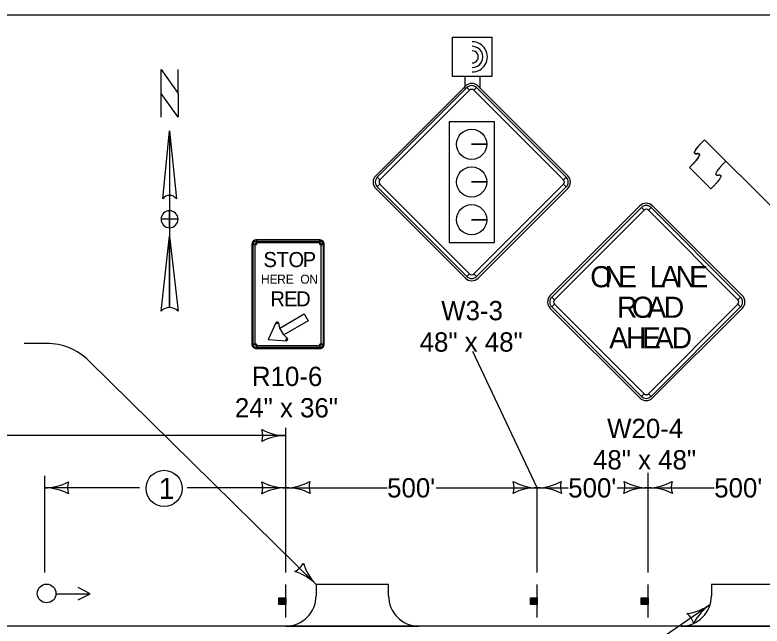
# Model space of a CAD drawing. Extents: x -2134934 to -2122394, y -2140205 to -2137036.
# Drawn here: x -2128036 to -2127418, y -2137542 to -2137036 of the extents above; entities that cross this region are included whole.
import ezdxf

# ---------------------------------------------------------------- set-up
doc = ezdxf.new("R2010")
doc.units = 0
for name, color, linetype in [('Barrier', 7, 'Continuous'), ('BridgeSuperStructureExisting', 7, 'Continuous'), ('Default', 7, 'Continuous'), ('dsnCellsScaleBlock', 7, 'Continuous'), ('DsnShtPlotIdentification', 7, 'Continuous'), ('DsnShtPlotShape', 7, 'Continuous'), ('TC_Barrier', 7, 'Continuous')]:
    doc.layers.add(name, color=color, linetype=linetype)

msp = doc.modelspace()

# ---------------------------------------------------------------- linework, layer by layer
at = {"layer": 'Barrier'}
for p, q in [((-2127663.33, -2137094.84), (-2127737.58, -2137169.09)), ((-2127662.01, -2137096.17), (-2127659.8, -2137098.38)), ((-2127656.26, -2137098.38), (-2127654.05, -2137096.17)), ((-2127578.48, -2137169.09), (-2127652.73, -2137094.84)), ((-2127645.62, -2137143.06), (-2127658.12, -2137143.06)), ((-2127658.12, -2137143.06), (-2127645.62, -2137143.06)), ((-2127407.97, -2137196.68), (-2127465.31, -2137139.38)), ((-2127465.31, -2137139.38), (-2127447.62, -2137157.06)), ((-2127460, -2137180.05), (-2127477.68, -2137162.37)), ((-2127734.04, -2137172.63), (-2127736.25, -2137170.42)), ((-2127579.81, -2137170.42), (-2127582.02, -2137172.63)), ((-2127737.58, -2137179.7), (-2127663.33, -2137253.94)), ((-2127736.25, -2137178.37), (-2127734.04, -2137176.16)), ((-2127645.62, -2137174.31), (-2127658.12, -2137174.31)), ((-2127658.12, -2137174.31), (-2127645.62, -2137174.31)), ((-2127652.73, -2137253.94), (-2127578.48, -2137179.7)), ((-2127582.02, -2137176.16), (-2127579.81, -2137178.37)), ((-2127518.85, -2137194.14), (-2127593.09, -2137268.39)), ((-2127517.52, -2137195.47), (-2127515.31, -2137197.68)), ((-2127511.78, -2137197.68), (-2127509.57, -2137195.47)), ((-2127433.99, -2137268.39), (-2127508.24, -2137194.14)), ((-2127645.62, -2137205.56), (-2127658.12, -2137205.56)), ((-2127658.12, -2137205.56), (-2127645.62, -2137205.56)), ((-2127836.37, -2137226.09), (-2127836.37, -2137222.34)), ((-2127836.37, -2137224.84), (-2127836.37, -2137223.27)), ((-2127783.87, -2137222.34), (-2127783.87, -2137226.09)), ((-2127783.87, -2137223.27), (-2127783.87, -2137224.84)), ((-2127840.12, -2137226.09), (-2127836.37, -2137226.09)), ((-2127839.18, -2137226.09), (-2127837.62, -2137226.09)), ((-2127783.87, -2137226.09), (-2127780.12, -2137226.09)), ((-2127782.62, -2137226.09), (-2127781.06, -2137226.09)), ((-2127659.8, -2137250.41), (-2127662.01, -2137252.62)), ((-2127654.05, -2137252.62), (-2127656.26, -2137250.41)), ((-2127589.56, -2137271.93), (-2127591.77, -2137269.72)), ((-2127435.32, -2137269.72), (-2127437.53, -2137271.93)), ((-2127593.09, -2137279), (-2127518.85, -2137353.24)), ((-2127591.77, -2137277.67), (-2127589.56, -2137275.46)), ((-2127508.24, -2137353.24), (-2127433.99, -2137279)), ((-2127437.53, -2137275.46), (-2127435.32, -2137277.67)), ((-2127820.26, -2137291.07), (-2127819.15, -2137291.65)), ((-2127819.15, -2137291.65), (-2127817.93, -2137291.38)), ((-2127810.81, -2137303.72), (-2127811.65, -2137304.64)), ((-2127836.37, -2137308.59), (-2127840.12, -2137308.59)), ((-2127837.62, -2137308.59), (-2127839.18, -2137308.59)), ((-2127836.37, -2137312.34), (-2127836.37, -2137308.59)), ((-2127836.37, -2137311.4), (-2127836.37, -2137309.84)), ((-2127811.65, -2137304.64), (-2127811.7, -2137305.89)), ((-2127780.12, -2137308.59), (-2127783.87, -2137308.59)), ((-2127783.87, -2137308.59), (-2127783.87, -2137312.34)), ((-2127783.87, -2137309.84), (-2127783.87, -2137311.4)), ((-2127781.06, -2137308.59), (-2127782.62, -2137308.59)), ((-2127515.31, -2137349.71), (-2127517.52, -2137351.92)), ((-2127509.57, -2137351.92), (-2127511.78, -2137349.71))]:
    msp.add_line(p, q, dxfattribs=at)
for points in [[(-2127662.01, -2137096.17), (-2127736.25, -2137170.42), (-2127734.04, -2137172.63), (-2127659.8, -2137098.38), (-2127662.01, -2137096.17)], [(-2127579.81, -2137170.42), (-2127654.05, -2137096.17), (-2127656.26, -2137098.38), (-2127582.02, -2137172.63), (-2127579.81, -2137170.42)], [(-2127639.3, -2137124.45), (-2127676.76, -2137124.45), (-2127676.76, -2137224.34), (-2127639.3, -2137224.34), (-2127639.3, -2137124.45)], [(-2127736.25, -2137178.37), (-2127662.01, -2137252.62), (-2127659.8, -2137250.41), (-2127734.04, -2137176.16), (-2127736.25, -2137178.37)], [(-2127654.05, -2137252.62), (-2127579.81, -2137178.37), (-2127582.02, -2137176.16), (-2127656.26, -2137250.41), (-2127654.05, -2137252.62)], [(-2127517.52, -2137195.47), (-2127591.77, -2137269.72), (-2127589.56, -2137271.93), (-2127515.31, -2137197.68), (-2127517.52, -2137195.47)], [(-2127435.32, -2137269.72), (-2127509.57, -2137195.47), (-2127511.78, -2137197.68), (-2127437.53, -2137271.93), (-2127435.32, -2137269.72)], [(-2127836.37, -2137312.34), (-2127783.87, -2137312.34), (-2127783.87, -2137308.59), (-2127780.12, -2137308.59), (-2127780.12, -2137226.09), (-2127783.87, -2137226.09), (-2127783.87, -2137222.34), (-2127836.37, -2137222.34), (-2127836.37, -2137226.09), (-2127840.12, -2137226.09), (-2127840.12, -2137308.59), (-2127836.37, -2137308.59), (-2127836.37, -2137312.34)], [(-2127783.87, -2137224.84), (-2127836.37, -2137224.84), (-2127836.37, -2137223.27), (-2127783.87, -2137223.27), (-2127783.87, -2137224.84)], [(-2127837.62, -2137226.09), (-2127837.62, -2137308.59), (-2127839.18, -2137308.59), (-2127839.18, -2137226.09), (-2127837.62, -2137226.09)], [(-2127782.62, -2137308.59), (-2127782.62, -2137226.09), (-2127781.06, -2137226.09), (-2127781.06, -2137308.59), (-2127782.62, -2137308.59)], [(-2127591.77, -2137277.67), (-2127517.52, -2137351.92), (-2127515.31, -2137349.71), (-2127589.56, -2137275.46), (-2127591.77, -2137277.67)], [(-2127509.57, -2137351.92), (-2127435.32, -2137277.67), (-2127437.53, -2137275.46), (-2127511.78, -2137349.71), (-2127509.57, -2137351.92)], [(-2127796.75, -2137283.59), (-2127793.47, -2137289.27), (-2127813.77, -2137300.99), (-2127817.05, -2137295.31), (-2127796.75, -2137283.59)], [(-2127826.77, -2137304.71), (-2127811.7, -2137305.89), (-2127811.65, -2137304.64), (-2127810.81, -2137303.72), (-2127813.77, -2137300.99), (-2127817.05, -2137295.31), (-2127817.93, -2137291.38), (-2127819.15, -2137291.65), (-2127820.26, -2137291.07), (-2127826.77, -2137304.71)], [(-2127836.37, -2137309.84), (-2127783.87, -2137309.84), (-2127783.87, -2137311.4), (-2127836.37, -2137311.4), (-2127836.37, -2137309.84)]]:
    msp.add_lwpolyline(points, close=True, dxfattribs=at)
for centre in [(-2127658.12, -2137143.06), (-2127658.12, -2137174.31), (-2127658.12, -2137205.56)]:
    msp.add_circle(centre, 12.5, dxfattribs=at)
for centre, radius, start, end in [((-2127658.03, -2137100.15), 7.5, 44.99999, 134.99974), ((-2127658.03, -2137100.15), 5.62, 44.99999, 134.99974), ((-2127658.03, -2137100.15), 2.5, 44.99999, 134.99974), ((-2127732.28, -2137174.39), 7.5, 134.99974, 224.99995), ((-2127732.28, -2137174.39), 5.62, 134.99974, 224.99995), ((-2127732.28, -2137174.39), 2.5, 134.99974, 224.99995), ((-2127583.79, -2137174.39), 2.5, 315.00016, 44.9998), ((-2127583.79, -2137174.39), 5.62, 315.00016, 44.9998), ((-2127583.79, -2137174.39), 7.5, 315.00016, 44.9998), ((-2127513.54, -2137199.45), 7.5, 44.99999, 134.99974), ((-2127513.54, -2137199.45), 5.62, 44.99999, 134.99974), ((-2127513.54, -2137199.45), 2.5, 44.99999, 134.99974), ((-2127836.37, -2137226.09), 3.75, 90.00021, 179.99985), ((-2127836.37, -2137226.09), 2.81, 90.00021, 179.99985), ((-2127783.87, -2137226.09), 3.75, 0, 90.00021), ((-2127783.87, -2137226.09), 2.81, 0, 90.00021), ((-2127836.37, -2137226.09), 1.25, 90.00021, 179.99985), ((-2127783.87, -2137226.09), 1.25, 0, 90.00021), ((-2127658.03, -2137248.64), 7.5, 224.99995, 315.00016), ((-2127658.03, -2137248.64), 5.62, 224.99995, 315.00016), ((-2127658.03, -2137248.64), 2.5, 224.99995, 315.00016), ((-2127587.79, -2137273.69), 7.5, 134.99974, 224.99995), ((-2127587.79, -2137273.69), 5.62, 134.99974, 224.99995), ((-2127587.79, -2137273.69), 2.5, 134.99974, 224.99995), ((-2127439.3, -2137273.69), 2.5, 315.00016, 44.9998), ((-2127439.3, -2137273.69), 5.62, 315.00016, 44.9998), ((-2127439.3, -2137273.69), 7.5, 315.00016, 44.9998), ((-2127819.15, -2137291.65), 1.25, 12.62232, 152.27557), ((-2127811.65, -2137304.64), 1.25, 267.72427, 47.37758), ((-2127836.37, -2137308.59), 3.75, 179.99985, 270.00006), ((-2127836.37, -2137308.59), 2.81, 179.99985, 270.00006), ((-2127836.37, -2137308.59), 1.25, 179.99985, 270.00006), ((-2127783.87, -2137308.59), 3.75, 270.00006, 0.00027), ((-2127783.87, -2137308.59), 2.81, 270.00006, 0.00027), ((-2127783.87, -2137308.59), 1.25, 270.00006, 0.00027), ((-2127513.54, -2137347.94), 7.5, 224.99995, 315.00016), ((-2127513.54, -2137347.94), 5.62, 224.99995, 315.00016), ((-2127513.54, -2137347.94), 2.5, 224.99995, 315.00016)]:
    msp.add_arc(centre, radius, start, end, dxfattribs=at)
for points in [[(-2127477.68, -2137162.37), (-2127465.31, -2137149.99), (-2127477.68, -2137151.77), (-2127465.31, -2137139.38)], [(-2127447.62, -2137157.06), (-2127460, -2137169.44), (-2127447.63, -2137167.67), (-2127460, -2137180.05)]]:
    msp.add_open_spline(points, degree=2, dxfattribs=at)
at = {"layer": 'BridgeSuperStructureExisting'}
for p, q in [((-2127663.87, -2137086.93), (-2127663.87, -2137096.93)), ((-2127651.37, -2137086.93), (-2127651.37, -2137096.93)), ((-2128010.17, -2137308.01), (-2128028.63, -2137308.01)), ((-2127603.79, -2137427.66), (-2127657.13, -2137314.86)), ((-2127975.09, -2137322.38), (-2127786.96, -2137507.67)), ((-2127811.95, -2137497.66), (-2127811.95, -2137377.91)), ((-2127811.95, -2137384.33), (-2128113.68, -2137384.33)), ((-2127511.96, -2137497.66), (-2127511.96, -2137415.16)), ((-2128011.93, -2137417.66), (-2128011.93, -2137497.66)), ((-2127933.15, -2137427.66), (-2128011.93, -2137427.66)), ((-2127811.93, -2137427.66), (-2127893.7, -2137427.66)), ((-2127811.95, -2137427.66), (-2127728.12, -2137427.66)), ((-2127687.62, -2137427.66), (-2127603.79, -2137427.66)), ((-2127603.79, -2137497.66), (-2127603.79, -2137427.66)), ((-2127603.79, -2137427.66), (-2127578.12, -2137427.66)), ((-2127537.62, -2137427.66), (-2127511.96, -2137427.66)), ((-2127511.96, -2137427.66), (-2127457.21, -2137427.66)), ((-2127811.95, -2137535.16), (-2127811.95, -2137507.66)), ((-2127603.79, -2137535.16), (-2127603.79, -2137507.66)), ((-2127511.96, -2137535.16), (-2127511.96, -2137507.66)), ((-2128002.38, -2137515.52), (-2127974.44, -2137515.52)), ((-2127817.28, -2137524.3), (-2127817.28, -2137518.71)), ((-2127816.96, -2137518.71), (-2127816.96, -2137524.3)), ((-2127816.74, -2137524.3), (-2127816.74, -2137518.71)), ((-2127816.42, -2137518.71), (-2127816.42, -2137524.3)), ((-2127816.19, -2137524.3), (-2127816.21, -2137518.71)), ((-2127815.78, -2137518.71), (-2127815.76, -2137524.3)), ((-2127815.56, -2137524.3), (-2127815.56, -2137518.71)), ((-2127815.12, -2137518.71), (-2127815.12, -2137524.3)), ((-2127814.75, -2137524.3), (-2127814.75, -2137518.71)), ((-2127814.43, -2137518.71), (-2127814.41, -2137524.3)), ((-2127814.21, -2137524.3), (-2127814.21, -2137518.71)), ((-2127813.94, -2137518.71), (-2127813.94, -2137524.3)), ((-2127813.61, -2137524.3), (-2127813.61, -2137518.71)), ((-2127813.4, -2137518.71), (-2127813.4, -2137524.3)), ((-2127813.17, -2137524.3), (-2127813.17, -2137518.71)), ((-2127812.91, -2137518.71), (-2127812.91, -2137524.3)), ((-2127812.65, -2137524.3), (-2127812.65, -2137518.71)), ((-2127812.37, -2137518.71), (-2127812.37, -2137524.3)), ((-2127609.12, -2137524.3), (-2127609.12, -2137518.71)), ((-2127608.8, -2137518.71), (-2127608.8, -2137524.3)), ((-2127608.58, -2137524.3), (-2127608.58, -2137518.71)), ((-2127608.26, -2137518.71), (-2127608.26, -2137524.3)), ((-2127608.03, -2137524.3), (-2127608.05, -2137518.71)), ((-2127607.62, -2137518.71), (-2127607.6, -2137524.3)), ((-2127607.4, -2137524.3), (-2127607.4, -2137518.71)), ((-2127606.96, -2137518.71), (-2127606.96, -2137524.3)), ((-2127606.59, -2137524.3), (-2127606.59, -2137518.71)), ((-2127606.27, -2137518.71), (-2127606.25, -2137524.3)), ((-2127606.05, -2137524.3), (-2127606.05, -2137518.71)), ((-2127605.78, -2137518.71), (-2127605.78, -2137524.3)), ((-2127605.45, -2137524.3), (-2127605.45, -2137518.71)), ((-2127605.24, -2137518.71), (-2127605.24, -2137524.3)), ((-2127605.01, -2137524.3), (-2127605.01, -2137518.71)), ((-2127604.75, -2137518.71), (-2127604.75, -2137524.3)), ((-2127604.49, -2137524.3), (-2127604.49, -2137518.71)), ((-2127604.21, -2137518.71), (-2127604.21, -2137524.3)), ((-2127517.28, -2137524.3), (-2127517.28, -2137518.71)), ((-2127516.96, -2137518.71), (-2127516.96, -2137524.3)), ((-2127516.74, -2137524.3), (-2127516.74, -2137518.71)), ((-2127516.42, -2137518.71), (-2127516.42, -2137524.3)), ((-2127516.19, -2137524.3), (-2127516.21, -2137518.71)), ((-2127515.78, -2137518.71), (-2127515.76, -2137524.3)), ((-2127515.56, -2137524.3), (-2127515.56, -2137518.71)), ((-2127515.13, -2137518.71), (-2127515.13, -2137524.3)), ((-2127514.75, -2137524.3), (-2127514.75, -2137518.71)), ((-2127514.43, -2137518.71), (-2127514.41, -2137524.3)), ((-2127514.21, -2137524.3), (-2127514.21, -2137518.71)), ((-2127513.94, -2137518.71), (-2127513.94, -2137524.3)), ((-2127513.61, -2137524.3), (-2127513.61, -2137518.71)), ((-2127513.4, -2137518.71), (-2127513.4, -2137524.3)), ((-2127513.18, -2137524.3), (-2127513.18, -2137518.71)), ((-2127512.91, -2137518.71), (-2127512.91, -2137524.3)), ((-2127512.65, -2137524.3), (-2127512.65, -2137518.71)), ((-2127512.37, -2137518.71), (-2127512.37, -2137524.3)), ((-2127823.33, -2137771.69), (-2127460.63, -2137524.39)), ((-2127811.96, -2137542.16), (-2127701.96, -2137542.16)), ((-2127484.56, -2137542.16), (-2127374.56, -2137542.16))]:
    msp.add_line(p, q, dxfattribs=at)
for points in [[(-2127673.87, -2137086.93), (-2127673.87, -2137054.43), (-2127641.37, -2137054.43), (-2127641.37, -2137086.93)], [(-2127812.05, -2137518.71), (-2127812.05, -2137524.34), (-2127817.67, -2137524.34), (-2127817.67, -2137518.71)], [(-2127603.89, -2137518.71), (-2127603.89, -2137524.34), (-2127609.51, -2137524.34), (-2127609.51, -2137518.71)], [(-2127512.05, -2137518.71), (-2127512.05, -2137524.34), (-2127517.68, -2137524.34), (-2127517.68, -2137518.71)]]:
    msp.add_lwpolyline(points, close=True, dxfattribs=at)
for points in [[(-2127726.96, -2137517.16), (-2127726.96, -2137507.67), (-2127786.96, -2137507.67), (-2127786.96, -2137517.16)], [(-2127399.56, -2137517.16), (-2127399.56, -2137507.67), (-2127459.56, -2137507.67), (-2127459.56, -2137517.16)], [(-2127984.07, -2137520.34), (-2127974.07, -2137515.34), (-2127984.07, -2137510.34)]]:
    msp.add_lwpolyline(points, dxfattribs=at)
for centre, radius in [((-2127912.79, -2137428.16), 15), ((-2128010.12, -2137515.16), 7.74)]:
    msp.add_circle(centre, radius, dxfattribs=at)
for centre, radius, start, end in [((-2127657.61, -2137070.7), 12.5, 269.40414, 90.54446), ((-2127657.61, -2137070.7), 12.5, 269.40414, 90.54446), ((-2127657.61, -2137070.7), 8.75, 269.40414, 90.54446), ((-2127657.61, -2137070.7), 5, 269.40414, 90.54446), ((-2128010.17, -2137358.01), 50, 45.43651, 90), ((-2128011.93, -2137385.16), 42.5, 270, 298.07249), ((-2128011.93, -2137470.16), 42.5, 61.92751, 90), ((-2127976.3, -2137427.66), 16.42, 162.26665, 197.73335), ((-2127847.57, -2137427.66), 16.42, 342.26665, 17.73335), ((-2127811.93, -2137385.16), 42.5, 241.92751, 270), ((-2127811.93, -2137470.16), 42.5, 90, 118.07249), ((-2127812.71, -2137385.17), 42.5, 271.0176, 299.07249), ((-2127811.23, -2137470.15), 42.5, 62.92751, 90.9824), ((-2127776.34, -2137427.04), 16.42, 163.26665, 198.73335), ((-2127639.41, -2137427.04), 16.42, 341.26665, 16.73335), ((-2127604.52, -2137470.15), 42.5, 89.0176, 117.07249), ((-2127603.04, -2137385.17), 42.5, 240.92751, 268.9824), ((-2127604.55, -2137385.17), 42.5, 271.0176, 299.07249), ((-2127603.07, -2137470.15), 42.5, 62.92751, 90.9824), ((-2127568.18, -2137427.04), 16.42, 163.26665, 198.73335), ((-2127547.57, -2137427.04), 16.42, 341.26665, 16.73335), ((-2127512.68, -2137470.15), 42.5, 89.0176, 117.07249), ((-2127511.2, -2137385.17), 42.5, 240.92751, 268.9824), ((-2127512.71, -2137385.17), 42.5, 271.0176, 299.07249), ((-2127511.23, -2137470.15), 42.5, 62.92751, 90.9824), ((-2127476.34, -2137427.04), 16.42, 163.26665, 198.73335), ((-2127811.96, -2137517.16), 25, 270, 0), ((-2127701.96, -2137517.16), 25, 180, 270), ((-2127484.56, -2137517.16), 25, 270, 0)]:
    msp.add_arc(centre, radius, start, end, dxfattribs=at)
at = {"layer": 'Default'}
msp.add_lwpolyline([(-2130231.95, -2137035.95), (-2127096.96, -2137035.95), (-2127096.96, -2139045.94), (-2130231.95, -2139045.94)], close=True, dxfattribs=at)
at = {"layer": 'dsnCellsScaleBlock'}
for p, q in [((-2127908.3, -2137131.92), (-2127902.67, -2137188.26)), ((-2127908.3, -2137131.92), (-2127908.3, -2137278.41)), ((-2127913.93, -2137188.26), (-2127913.93, -2137188.26)), ((-2127913.72, -2137187.74), (-2127912.67, -2137186.56)), ((-2127908.3, -2137212.2), (-2127908.3, -2137212.21)), ((-2127915.34, -2137281.23), (-2127908.3, -2137219.25))]:
    msp.add_line(p, q, dxfattribs=at)
msp.add_lwpolyline([(-2127901.26, -2137120.65), (-2127915.34, -2137100.93), (-2127915.34, -2137081.21), (-2127901.26, -2137100.93)], close=True, dxfattribs=at)
for points in [[(-2127915.34, -2137120.65), (-2127915.34, -2137081.21), (-2127901.26, -2137100.93), (-2127901.26, -2137081.21)], [(-2127913.93, -2137188.26), (-2127908.3, -2137131.92), (-2127908.3, -2137185.44)], [(-2127901.26, -2137205.16), (-2127908.3, -2137205.16), (-2127908.3, -2137198.12)], [(-2127908.3, -2137212.21), (-2127908.3, -2137205.16), (-2127915.34, -2137205.16)], [(-2127908.3, -2137278.41), (-2127908.3, -2137219.25), (-2127901.26, -2137281.22)]]:
    msp.add_lwpolyline(points, dxfattribs=at)
for centre, radius, start, end in [((-2127908.3, -2137192.49), 7.04, 90.02039, 143.12574), ((-2127908.3, -2137192.48), 7.04, 36.84806, 90.02184), ((-2127908.3, -2137205.16), 7.04, 90, 180), ((-2127908.3, -2137205.16), 7.04, 360, 90), ((-2127908.3, -2137205.16), 7.04, 180, 270), ((-2127908.3, -2137205.16), 7.04, 270, 360), ((-2127908.3, -2137288.61), 10.2, 89.98939, 133.61895), ((-2127908.3, -2137288.62), 10.21, 46.40206, 90.00064)]:
    msp.add_arc(centre, radius, start, end, dxfattribs=at)
at = {"layer": 'DsnShtPlotIdentification'}
msp.add_line((-2127160.12, -2137542.16), (-2128660.12, -2137542.16), dxfattribs=at)
msp.add_line((-2127160.12, -2137542.16), (-2128660.12, -2137542.16), dxfattribs=at)
at = {"layer": 'DsnShtPlotShape'}
for centre, radius, start, end in [((-2127847.59, -2137384.37), 16.42, 342.26665, 17.73335), ((-2127811.95, -2137341.87), 42.5, 241.92751, 270), ((-2127811.95, -2137426.87), 42.5, 90, 118.07249), ((-2127812.04, -2137482.35), 16.42, 296.997, 332.46371), ((-2127756.76, -2137477.76), 42.5, 196.65786, 224.73035), ((-2127817.15, -2137537.58), 42.5, 44.73035, 72.80284), ((-2127485, -2137489.57), 42.5, 276.9218, 304.99429), ((-2127436.25, -2137559.2), 42.5, 124.99429, 153.06678), ((-2127489.82, -2137544.82), 16.42, 17.26094, 52.72764)]:
    msp.add_arc(centre, radius, start, end, dxfattribs=at)
at = {"layer": 'TC_Barrier'}
msp.add_line((-2127477.68, -2137162.37), (-2127460, -2137180.05), dxfattribs=at)
for points in [[(-2127465.31, -2137139.38), (-2127477.68, -2137151.77), (-2127465.31, -2137149.99), (-2127477.68, -2137162.37)], [(-2127447.62, -2137157.06), (-2127460, -2137169.44), (-2127447.63, -2137167.67), (-2127460, -2137180.05)]]:
    msp.add_open_spline(points, degree=2, dxfattribs=at)

# ---------------------------------------------------------------- texts
at = {"layer": 'Barrier'}
for s, height, p in [('S', 12.5, (-2127830.57, -2137244.84)), ('T', 12.5, (-2127819.8, -2137244.84)), ('O', 12.5, (-2127809.82, -2137244.84)), ('P', 12.5, (-2127798.07, -2137244.84)), ('O', 17.5, (-2127559.83, -2137261.51)), ('N', 17.5, (-2127548.05, -2137261.51)), ('E', 17.5, (-2127536.83, -2137261.51)), ('L', 17.5, (-2127510.58, -2137261.51)), ('A', 17.5, (-2127501.38, -2137261.51)), ('N', 17.5, (-2127489.11, -2137261.51)), ('E', 17.5, (-2127477.88, -2137261.51)), ('H', 7.5, (-2127832.64, -2137258.59)), ('E', 7.5, (-2127825.49, -2137258.59)), ('R', 7.5, (-2127819.24, -2137258.59)), ('E', 7.5, (-2127812.09, -2137258.59)), ('O', 7.5, (-2127800.02, -2137258.59)), ('N', 7.5, (-2127792.63, -2137258.59)), ('R', 12.5, (-2127824.81, -2137277.34)), ('E', 12.5, (-2127813.48, -2137277.34)), ('D', 12.5, (-2127803.52, -2137277.34)), ('W3-3', 16, (-2127683.32, -2137288.86)), ('R', 17.5, (-2127537.72, -2137286.82)), ('O', 17.5, (-2127525.43, -2137286.82)), ('A', 17.5, (-2127512.59, -2137286.82)), ('D', 17.5, (-2127498.94, -2137286.82)), ('A', 17.5, (-2127544.16, -2137312.13)), ('H', 17.5, (-2127530.29, -2137312.13)), ('E', 17.5, (-2127517.08, -2137312.13)), ('A', 17.5, (-2127506.36, -2137312.13)), ('D', 17.5, (-2127492.5, -2137312.13)), ('48" x 48"', 16, (-2127701.2, -2137314.86)), ('R10-6', 16, (-2127840.05, -2137343.34)), ('24" x 36"', 16, (-2127854.19, -2137369.34)), ('W20-4', 16, (-2127545.91, -2137386.44)), ('48" x 48"', 16, (-2127557.61, -2137412.44))]:
    msp.add_text(s, height=height, dxfattribs=at).set_placement(p)
at = {"layer": 'BridgeSuperStructureExisting'}
for s, height, p in [('1', 17.5, (-2127917.25, -2137436.91)), ("500'", 16, (-2127728.12, -2137435.66)), ("500'", 16, (-2127578.12, -2137435.66)), ("500'", 16, (-2127457.21, -2137435.66))]:
    msp.add_text(s, height=height, dxfattribs=at).set_placement(p)

doc.saveas('drawing.dxf')
